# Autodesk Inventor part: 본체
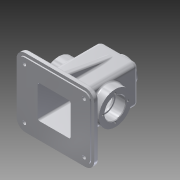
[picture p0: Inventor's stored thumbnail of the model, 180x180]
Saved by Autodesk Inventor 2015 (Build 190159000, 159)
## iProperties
Created: 2016-02
Part Number: 본체
Material: 알루미늄 6061
Document SubType Name: Modeling
Designer: Administrator
Density: 2.7 g/cm^3
Appearance: 알루미늄 - 평지
Author: Administrator
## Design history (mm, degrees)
sketch "스케치1"
  geometry: L1 (-65, 57.5)-(65, 57.5); L2 (65, 57.5)-(65, -57.5); L3 (65, -57.5)-(-65, -57.5); L4 (-65, -57.5)-(-65, 57.5); L5 (-65, 57.5)-(65, -57.5); L6 (65, 57.5)-(-65, -57.5); 1 further point
  constraints: 12 end point, 2 midpoint, 2 parallel, 1 horizontal, 1 perpendicular
  dimensions: "d0" = 115 distance of L1.end L2.end; "d1" = 130 distance of L1.start L1.end
extrude "돌출1" new body sketch "스케치1" distance "d2" = 8; taper "d3" = 0 deg
sketch "스케치2"
  geometry: L1 (-60, -52.5)-(60, -52.5); L2 (60, -52.5)-(60, 52.5); L3 (60, 52.5)-(-60, 52.5); L4 (-60, 52.5)-(-60, -52.5); L5 (-60, -52.5)-(60, 52.5); L6 (60, -52.5)-(-60, 52.5); 1 further point
  constraints: 12 end point, 2 midpoint, 2 parallel, 1 horizontal, 1 perpendicular
  dimensions: "d4" = 120 distance of L2.end L3.end; "d5" = 105 distance of L1.end L2.end
extrude "돌출2" join sketch "스케치2" distance "d6" = 2; taper "d7" = 0 deg
sketch "스케치3"
  geometry: L1 (32.5, 32.5)-(-32.5, 32.5); L2 (-32.5, 32.5)-(-32.5, -32.5); L3 (-32.5, -32.5)-(32.5, -32.5); L4 (32.5, -32.5)-(32.5, 32.5); L5 (32.5, 32.5)-(-32.5, -32.5); L6 (-32.5, 32.5)-(32.5, -32.5); 1 further point
  constraints: 12 end point, 2 midpoint, 2 parallel, 1 horizontal, 1 perpendicular
  dimensions: "d8" = 65 distance of L2.end L3.end; "d9" = 65 distance of L1.end L2.end
extrude "돌출3" join sketch "스케치3" distance "d10" = 100; taper "d11" = 0 deg
node "작업 평면1"
sketch "스케치4"
  geometry: L1 (-2, -52.5)-(-2, 52.5) reference; C1 r 27.5 at (53, 0); 1 further point
  constraints: 1 centre point, 1 horizontal alignment
  dimensions: "d13" = 55 diameter of C1; "d14" = 55 distance from line of L1 C1.centre
extrude "돌출4" join sketch "스케치4" stored distance "d15" = 100; taper "d16" = 0 deg
node "작업 평면2"
sketch "스케치5"
  geometry: C1 r 20 at (0, 0); 1 further point
  constraints: 1 centre point, 1 coincident
  dimensions: "d18" = 40 diameter of C1
extrude "돌출5" join sketch "스케치5" stored distance "d19" = 100; taper "d20" = 5 deg
hole "구멍1" diameter "d23" = 35; stored, may be unused: countersink angle "d27" = 90 deg, drill point angle "d29" = 0 deg; dims "d21" = 10, "d22" = 10, "d24" = 6, "d25" = 4, "d26" = 2, "d28" = 17
hole "구멍2" diameter "d32" = 30; stored, may be unused: countersink angle "d36" = 90 deg, drill point angle "d38" = 0 deg; dims "d30" = 10, "d31" = 10, "d33" = 6, "d34" = 4, "d35" = 2, "d37" = 3
sketch "스케치6"
  geometry: L1 (27.5, -27.5)-(-27.5, -27.5); L2 (-27.5, -27.5)-(-27.5, 27.5); L3 (-27.5, 27.5)-(27.5, 27.5); L4 (27.5, 27.5)-(27.5, -27.5); L5 (27.5, -27.5)-(-27.5, 27.5); L6 (-27.5, -27.5)-(27.5, 27.5); 1 further point
  constraints: 12 end point, 2 midpoint, 2 parallel, 1 horizontal, 1 perpendicular
  dimensions: "d39" = 55 distance of L1.end L2.end; "d40" = 55 distance of L2.end L3.end
extrude "돌출6" cut sketch "스케치6" distance "d41" = 105; taper "d42" = 0 deg
hole "구멍3" diameter "d45" = 21; stored, may be unused: countersink angle "d49" = 90 deg, drill point angle "d51" = 0 deg; dims "d43" = 10, "d44" = 10, "d46" = 6, "d47" = 4, "d48" = 2, "d50" = 20
sketch "스케치7" dims "d53" = 42
  geometry: L1 (-52.5, -55)-(52.5, -55) reference; C1 r 2 at (0, 21); C2 r 2 at (-21, 0); C3 r 2 at (0, -21); C4 r 2 at (21, 0); 2 further points
  constraints: 4 centre point, 2 vertical alignment, 11 other
  dimensions: "d54" = 55 distance from line of L1 point (0, 0); "d55" = 4 diameter of C1; "d57" = 76 distance from line of L1 C1.centre; "d60" = 360 deg dimension on point (0, 0) C1.centre (derived)
hole "구멍4" sketch "스케치7" at (0, 21), (-21, 0), (0, -21), (21, 0) diameter "d62" = 3.242; stored, may be unused: countersink angle "d66" = 90 deg, drill point angle "d68" = 118 deg; dims "d63" = 8, "d64" = 4, "d65" = 2, "d67" = 10
sketch "스케치8" dims "d69" = 29
  geometry: C1 r 1.5 at (0, 14.5); C2 r 1.5 at (-14.5, 0); C3 r 1.5 at (0, -14.5); C4 r 1.5 at (14.5, 0); 2 further points
  constraints: 4 centre point, 2 vertical alignment, 1 coincident, 11 other
  dimensions: "d70" = 3 diameter of C1; "d73" = 360 deg dimension on point (0, 0) C1.centre (derived)
hole "구멍5" sketch "스케치8" at (0, -14.5), (-14.5, 0), (14.5, 0), (0, 14.5) diameter "d75" = 2.459; stored, may be unused: countersink angle "d79" = 90 deg, drill point angle "d81" = 118 deg; dims "d76" = 7, "d77" = 4, "d78" = 2, "d80" = 9
sketch "스케치9"
  geometry: L1 (-60, 52.5)-(-60, -52.5) reference; L2 (-60, -52.5)-(60, -52.5) reference; L3 (60, -52.5)-(60, 52.5) reference; L4 (60, 52.5)-(-60, 52.5) reference; L5 (65, -57.5)-(-65, -57.5) reference; L6 (-65, -57.5)-(-65, 57.5) reference; L7 (-65, 57.5)-(65, 57.5) reference; L8 (65, 57.5)-(65, -57.5) reference; L9 (0, 0)-(0, -66.144); L10 (0, 0)-(-52.298, 0); C1 r 7.5 at (-50, -42.5); C2 r 7.5 at (-50, 42.5); C3 r 7.5 at (50, -42.5); C4 r 7.5 at (50, 42.5)
  constraints: 4 centre point, 4 end point, 3 symmetric about line, 1 horizontal, 1 vertical, 3 other
  dimensions: "d82" = 15 diameter of C1; "d83" = 15 distance from line of C1.centre L6; "d84" = 15 distance from line of L5 C1.centre
extrude "돌출7" join sketch "스케치9" distance "d85" = 3; taper "d86" = 0 deg
sketch "스케치10"
  geometry: L1 (50, 42.5)-(-7.031, 42.5); L2 (50, 42.5)-(50, -23.271); C1 r 7.5 at (0, 0) reference; C2 r 3 at (0, 0); C3 r 3 at (0, 85); C4 r 3 at (100, 0); C5 r 3 at (100, 85)
  constraints: 4 centre point, 4 end point, 3 symmetric about line, 1 coincident, 1 horizontal, 1 vertical, 3 other
  dimensions: "d88" = 6 diameter of C2
hole "구멍6" sketch "스케치10" at (0, 0), (100, 0), (100, 85), (0, 85) diameter "d89" = 6; stored, may be unused: countersink angle "d93" = 90 deg, drill point angle "d95" = 0 deg; dims "d90" = 7, "d91" = 4, "d92" = 2, "d94" = 9
sketch "스케치12"
  geometry: L1 (8, 32.5)-(108, 32.5) reference; L2 (8, -57.5)-(8, 57.5) reference; L3 (8, 47.5)-(93.069, 32.5); L4 (8, 32.5)-(8, 47.5); L5 (93.069, 32.5)-(8, 32.5); L6 (0, 57.5)-(8, 57.5) reference; 1 further point
  constraints: 6 end point, 2 point on line, 1 collinear, 1 perpendicular
  dimensions: "d98" = 10 deg angle of L3 L6; "d99" = 10 distance from line of L6 L3.start
extrude "돌출8" join sketch "스케치12" stored distance "d100" = 10; taper "d101" = 0 deg
sketch "스케치13"
  geometry: L1 (32.5, 8)-(32.5, 108) reference; L2 (32.5, 8)-(42.5, 8); L3 (42.5, 8)-(42.5, 28); L4 (42.5, 28)-(32.5, 28); L5 (32.5, 28)-(32.5, 8); L6 (27.5, -2)-(27.5, 103) reference; 1 further point
  constraints: 8 end point, 2 parallel, 1 horizontal, 1 perpendicular, 1 point on line
  dimensions: "d102" = 15 distance between parallel lines of L3 L6; "d117" = 20 distance of L2.end L3.end
extrude "돌출9" join sketch "스케치13" stored distance "d103" = 6; taper "d104" = 0 deg
chamfer "모따기1" distance "d105" = 1; stored, may be unused: second distance "d106" = 2, angle "d107" = 45 deg
chamfer "모따기2" distance "d108" = 1; stored, may be unused: second distance "d109" = 2, angle "d110" = 45 deg
fillet "모깎기1" dims "d111" = 15
fillet "모깎기2" dims "d112" = 15
fillet "모깎기3" dims "d113" = 15
fillet "모깎기4" dims "d114" = 15
fillet "모깎기5" dims "d115" = 2.5
fillet "모깎기6" dims "d116" = 2.5
fillet "모깎기7"
fillet "모깎기8"
fillet "모깎기9" dims "d118" = 3
fillet "모깎기10" dims "d119" = 3
fillet "모깎기11" dims "d120" = 3
fillet "모깎기12" dims "d121" = 3
fillet "모깎기13" dims "d123" = 8
fillet "모깎기14" dims "d124" = 8
fillet "모깎기15" dims "d125" = 3
fillet "모깎기16" dims "d126" = 3
fillet "모깎기17" dims "d127" = 3
fillet "모깎기19" dims "d129" = 3
fillet "모깎기20" dims "d130" = 3
fillet "모깎기21" dims "d131" = 3
fillet "모깎기22" dims "d132" = 3
fillet "모깎기23" dims "d133" = 1
fillet "모깎기24" dims "d134" = 3
fillet "모깎기25" dims "d135" = 0.3
fillet "모깎기26" dims "d136" = 3
sketch "스케치14"
  geometry: L1 (-8, 0)-(-8, -91) reference; L2 (77, -102)-(-28, -102) reference; L3 (4.5, 18)-(44.5, 18) reference; C1 r 15 at (24.5, -47) reference; 2 further points
  constraints: 1 other
  dimensions: "d137" = 32.5 distance from line of L1 point (24.5, -8); "d139" = 26 distance from line of point (24.5, -8) L3
feature "엠보싱1" sketch "스케치14" dims "d140" = 0.5, "d141" = 0
fillet "모깎기27" dims "d142" = 10
node "솔리드1"
mirror "대칭1"
mirror "대칭2"
mirror "대칭3"
mirror "대칭4"
mirror "대칭5"
mirror "대칭6"
node "투영된 루프1"
other parameters: "d12" = -47.5, "d17" = 118
